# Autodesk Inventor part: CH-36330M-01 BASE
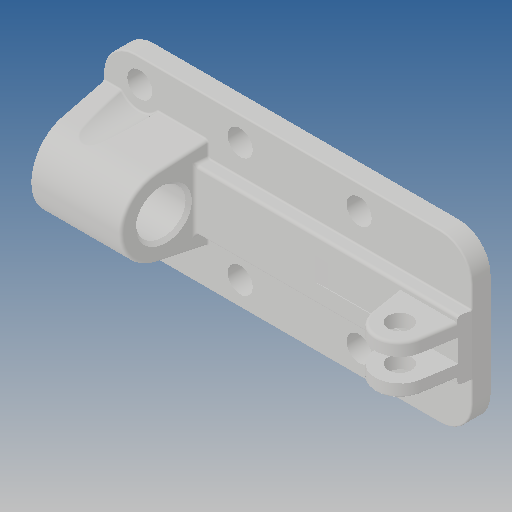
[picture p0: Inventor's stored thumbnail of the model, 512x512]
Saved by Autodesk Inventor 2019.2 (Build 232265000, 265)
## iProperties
Created: 2012-09
Part Number: CH-36330M-01 BASE
Material: Ogólny
Document SubType Name: Modeling
Designer: CADENGINEERING4
Density: 1 g/cm^3
Appearance: Domyślna
Author: CADENGINEERING4
Revision Number: ÈÎºÎ
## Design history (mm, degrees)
feature "Ô²½Ç9"
node "Bryła1"
